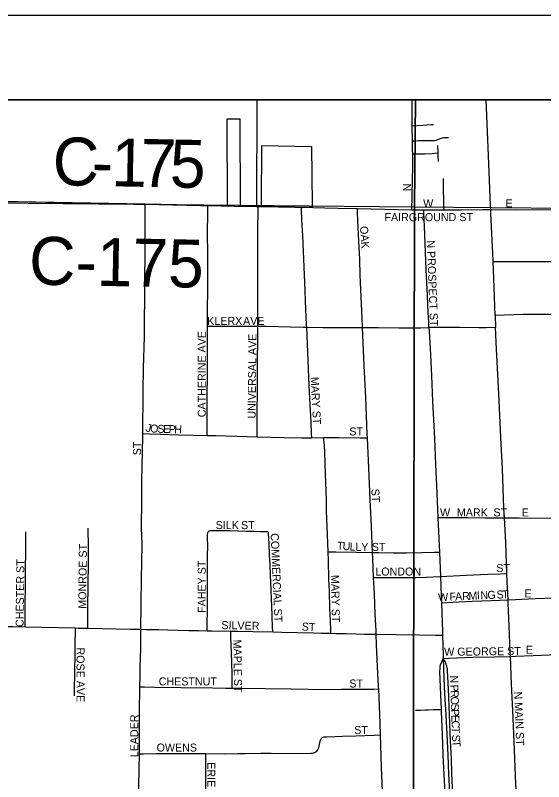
# Model space of a CAD drawing. Extents: x -9.1 to 34, y -3.1 to 22.
# Drawn here: x 4.755 to 5.381, y 20.093 to 21 of the extents above; entities that cross this region are included whole.
import ezdxf

# ---------------------------------------------------------------- set-up
doc = ezdxf.new("R2010")
doc.units = 0
for name, color, linetype in [('GM_X_City_Street', 7, 'Continuous'), ('GM_X_City_Street_Text', 7, 'Continuous'), ('GM_X_Corporation', 7, 'Continuous'), ('GM_X_County_Road', 7, 'Continuous'), ('GM_X_County_Road_Text', 7, 'Continuous'), ('GM_X_Section', 7, 'Continuous'), ('GM_X_State_Route', 7, 'Continuous'), ('SH_Data', 7, 'Continuous')]:
    doc.layers.add(name, color=color, linetype=linetype)

msp = doc.modelspace()

# ---------------------------------------------------------------- linework, layer by layer
at = {"layer": 'GM_X_City_Street'}
for points in [[(5.22551, 20.86936), (5.22535, 20.88109), (5.22533, 20.89662), (5.22534, 20.9)], [(5.22551, 20.86936), (5.23142, 20.86962), (5.23781, 20.86991), (5.24737, 20.87077), (5.25057, 20.8708)], [(5.22575, 20.85146), (5.22551, 20.86936)], [(5.22575, 20.85146), (5.22951, 20.85164), (5.23291, 20.8518), (5.23571, 20.85175), (5.23851, 20.8517), (5.24949, 20.85167), (5.25058, 20.85175), (5.25164, 20.85183), (5.25358, 20.85214), (5.2567, 20.85341), (5.25789, 20.85398), (5.25871, 20.85428), (5.26011, 20.85478), (5.26134, 20.85512), (5.26297, 20.85535), (5.26511, 20.85535), (5.26818, 20.85544)], [(5.22597, 20.836), (5.22589, 20.8408), (5.22575, 20.85146)], [(5.25607, 20.83729), (5.25577, 20.84606)], [(5.22506, 20.76989), (5.22511, 20.77377), (5.22522, 20.78184), (5.22578, 20.80969), (5.22595, 20.81592), (5.22591, 20.82836), (5.226, 20.83454), (5.22597, 20.836)], [(5.22597, 20.836), (5.23091, 20.83597), (5.23989, 20.83592), (5.2489, 20.83659), (5.2519, 20.83688), (5.25607, 20.83729)], [(5.2564, 20.827), (5.25622, 20.83362), (5.25607, 20.83729)], [(5.26304, 20.76986), (5.26293, 20.77345), (5.26274, 20.78039), (5.26259, 20.79335), (5.26251, 20.79976), (5.26243, 20.80683)], [(4.90602, 20.50486), (4.90656, 20.55459), (4.90695, 20.58236), (4.908, 20.61929), (4.90852, 20.68454), (4.90904, 20.72028), (4.90903, 20.75136), (4.90903, 20.77183), (4.90903, 20.77635)], [(4.98285, 20.63214), (4.9829, 20.64625), (4.98294, 20.6548), (4.98304, 20.6718), (4.9831, 20.68226), (4.98314, 20.69724), (4.98311, 20.71109), (4.98308, 20.72191), (4.98296, 20.73741), (4.98312, 20.7703), (4.98315, 20.77476)], [(5.04074, 20.77381), (5.04276, 20.77379)], [(5.04233, 20.63207), (5.04236, 20.63902), (5.04241, 20.65127), (5.0423, 20.66875), (5.0424, 20.68633), (5.0425, 20.70587), (5.0424, 20.72736), (5.04232, 20.74518), (5.0427, 20.76977), (5.04276, 20.77379)], [(5.04276, 20.77379), (5.04737, 20.77376)], [(5.10035, 20.63083), (5.10019, 20.63356), (5.09898, 20.6616), (5.09849, 20.67421), (5.09775, 20.69302), (5.09561, 20.73888), (5.09478, 20.75802), (5.09431, 20.76973), (5.09418, 20.77276)], [(5.10749, 20.77249), (5.12198, 20.77205), (5.1375, 20.77165), (5.15928, 20.77135), (5.16054, 20.77132)], [(5.16651, 20.63046), (5.16602, 20.64144), (5.16372, 20.69253), (5.16312, 20.71101), (5.16228, 20.73259), (5.16105, 20.75722), (5.16071, 20.76651), (5.16054, 20.77132)], [(5.16054, 20.77132), (5.20904, 20.77002), (5.22506, 20.76989)], [(5.22506, 20.76989), (5.23391, 20.76983), (5.23907, 20.76983)], [(5.23907, 20.76983), (5.26304, 20.76986)], [(5.24521, 20.6304), (5.24489, 20.63631), (5.24452, 20.64318), (5.24427, 20.64765), (5.24338, 20.66855), (5.24208, 20.69885), (5.2398, 20.75025), (5.2392, 20.76633), (5.23907, 20.76983)], [(5.26304, 20.76986), (5.28369, 20.76989), (5.30917, 20.77016), (5.31853, 20.77025)], [(5.31853, 20.77025), (5.34775, 20.76989), (5.39737, 20.77016), (5.39918, 20.77018)], [(5.32126, 20.70844), (5.33072, 20.70845), (5.38395, 20.70852), (5.40252, 20.7086)], [(4.98227, 20.50274), (4.98229, 20.50622), (4.98237, 20.5204), (4.98247, 20.53842), (4.98257, 20.55462), (4.98265, 20.56937), (4.98273, 20.58299), (4.98276, 20.60111), (4.9828, 20.61788), (4.98285, 20.63214)], [(4.98285, 20.63214), (4.98731, 20.63214), (5.03057, 20.63214), (5.04233, 20.63207)], [(5.04163, 20.50121), (5.04165, 20.50628), (5.04174, 20.52277), (5.0418, 20.53321), (5.04191, 20.55247), (5.0422, 20.58025), (5.04225, 20.59267), (5.04235, 20.61418), (5.04231, 20.6265), (5.04233, 20.63207)], [(5.04233, 20.63207), (5.05221, 20.63201), (5.08118, 20.63122), (5.09638, 20.63091), (5.10035, 20.63083)], [(5.10035, 20.63083), (5.11935, 20.63067), (5.13499, 20.63063), (5.16651, 20.63046)], [(5.10626, 20.50006), (5.10607, 20.50474), (5.10553, 20.51841), (5.10423, 20.54636), (5.10341, 20.56189), (5.10035, 20.63083)], [(5.16651, 20.63046), (5.16942, 20.63042), (5.18501, 20.63032), (5.2096, 20.63016), (5.22553, 20.63005), (5.23574, 20.62999), (5.24521, 20.6304)], [(5.17236, 20.50007), (5.17216, 20.50434), (5.17031, 20.54762), (5.16859, 20.5851), (5.16732, 20.61254), (5.16651, 20.63046)], [(5.33461, 20.40522), (5.33402, 20.41672), (5.33223, 20.46309), (5.33045, 20.50019), (5.32841, 20.54399), (5.32678, 20.57476), (5.32519, 20.60477), (5.32412, 20.63035)], [(4.90482, 20.3986), (4.90487, 20.42089), (4.90509, 20.44886), (4.90601, 20.50162), (4.90602, 20.50486)], [(4.90602, 20.50486), (4.91394, 20.50459), (4.92718, 20.50415), (4.94897, 20.50348), (4.98227, 20.50274)], [(4.98227, 20.50274), (4.99258, 20.50251), (5.02994, 20.50155), (5.04163, 20.50121)], [(5.04163, 20.50121), (5.0735, 20.50029), (5.09416, 20.49994), (5.10626, 20.50006)], [(5.12035, 20.5002), (5.12166, 20.50021), (5.13872, 20.50041), (5.16361, 20.50008), (5.16671, 20.50008), (5.17236, 20.50007)], [(5.10626, 20.50006), (5.12035, 20.5002)], [(5.12569, 20.36507), (5.12464, 20.39495), (5.12422, 20.4042), (5.12401, 20.41352), (5.12369, 20.42598), (5.1228, 20.45721), (5.12191, 20.48225), (5.12132, 20.49103), (5.12035, 20.5002)], [(5.17838, 20.36421), (5.17706, 20.39489), (5.17553, 20.42699), (5.17402, 20.46409), (5.17236, 20.50007)], [(5.25584, 20.40548), (5.26048, 20.40548), (5.27289, 20.40548), (5.29121, 20.40549), (5.31138, 20.40534), (5.32267, 20.40538), (5.33461, 20.40522)], [(5.33461, 20.40522), (5.3385, 20.40522), (5.35252, 20.40522), (5.36568, 20.405), (5.38586, 20.40508), (5.40301, 20.40493), (5.41499, 20.40452)], [(5.3376, 20.33914), (5.3361, 20.37607), (5.33461, 20.40522)], [(4.84109, 20.27454), (4.84113, 20.27918), (4.8412, 20.28724), (4.84117, 20.29662), (4.8412, 20.30563), (4.84125, 20.31792), (4.84137, 20.33086), (4.84173, 20.34585), (4.8417, 20.35834), (4.84168, 20.37051), (4.84151, 20.39304)], [(4.90387, 20.27331), (4.90408, 20.30295), (4.90454, 20.33315), (4.90483, 20.35268), (4.90529, 20.37429), (4.90481, 20.39292), (4.90482, 20.3986)], [(4.76668, 20.27618), (4.76666, 20.28193), (4.76661, 20.30035), (4.76716, 20.32787), (4.76729, 20.34914), (4.76739, 20.36129), (4.76747, 20.38575), (4.76747, 20.38879)], [(4.98252, 20.27154), (4.98262, 20.28002), (4.98283, 20.2955), (4.98286, 20.31084), (4.9828, 20.3475), (4.98298, 20.35979), (4.98302, 20.37209), (4.98296, 20.38135), (4.98298, 20.38571), (4.983, 20.38643), (4.98308, 20.38713), (4.98324, 20.38765), (4.98344, 20.38813), (4.98392, 20.38898)], [(4.98392, 20.38898), (4.98432, 20.38937), (4.98487, 20.38975), (4.98538, 20.38998), (4.98598, 20.39011), (4.98665, 20.39018), (4.9876, 20.39016), (4.99273, 20.39015), (5.00022, 20.39009), (5.00958, 20.39002), (5.02861, 20.38953), (5.03808, 20.38932), (5.04545, 20.38916), (5.05039, 20.38912), (5.0523, 20.38908), (5.05341, 20.38893), (5.05416, 20.38869), (5.05465, 20.38824)], [(5.06009, 20.27013), (5.05991, 20.27612), (5.05916, 20.3011), (5.05883, 20.30797), (5.05829, 20.31998), (5.05754, 20.33703), (5.057, 20.34969), (5.05642, 20.36118), (5.05582, 20.37485), (5.05517, 20.38684), (5.05497, 20.38767), (5.05465, 20.38824)], [(5.12908, 20.26857), (5.12894, 20.2719), (5.12845, 20.28383), (5.12787, 20.29803), (5.12721, 20.31834), (5.12674, 20.33277), (5.12606, 20.35459), (5.12569, 20.36507)], [(5.12569, 20.36507), (5.12886, 20.36498), (5.13485, 20.36481), (5.15919, 20.36454), (5.17838, 20.36421)], [(5.17838, 20.36421), (5.18529, 20.36406), (5.20274, 20.3638), (5.21856, 20.36374), (5.23659, 20.36404), (5.25181, 20.3645), (5.25758, 20.3647)], [(5.17966, 20.33462), (5.17869, 20.35713), (5.17838, 20.36421)], [(5.25873, 20.33586), (5.28917, 20.33716), (5.31505, 20.33834), (5.32975, 20.33886), (5.3376, 20.33914)], [(5.33887, 20.30775), (5.33798, 20.3295), (5.3376, 20.33914)], [(5.17966, 20.33462), (5.18612, 20.33455), (5.19236, 20.33448), (5.20801, 20.33444), (5.22987, 20.3346), (5.24199, 20.33513), (5.25793, 20.33581), (5.25873, 20.33586)], [(5.18264, 20.26743), (5.18249, 20.27137), (5.18157, 20.2915), (5.1805, 20.31518), (5.17966, 20.33462)], [(5.41873, 20.31105), (5.4052, 20.3105), (5.37122, 20.30913), (5.35541, 20.30845), (5.3479, 20.30813), (5.33887, 20.30775)], [(5.33887, 20.30775), (5.31948, 20.30714), (5.29644, 20.30607), (5.27297, 20.30515), (5.2667, 20.30477), (5.25991, 20.30437)], [(5.34109, 20.25534), (5.34047, 20.26804), (5.339, 20.30435), (5.33887, 20.30775)], [(4.69403, 20.27766), (4.70576, 20.2774), (4.73368, 20.27677), (4.75233, 20.27643), (4.76668, 20.27618)], [(4.76668, 20.27618), (4.78652, 20.27584), (4.82656, 20.27484)], [(4.82515, 20.19451), (4.82535, 20.20704), (4.82552, 20.216), (4.82577, 20.22877), (4.82588, 20.23811), (4.82591, 20.24146), (4.82604, 20.25655), (4.82646, 20.27194), (4.82656, 20.27484)], [(4.82656, 20.27484), (4.82999, 20.27476), (4.84109, 20.27454)], [(4.84109, 20.27454), (4.89178, 20.27354), (4.90387, 20.27331)], [(4.90254, 20.2051), (4.90286, 20.21753), (4.90315, 20.22872), (4.9037, 20.25021), (4.90387, 20.27331)], [(4.90387, 20.27331), (4.91056, 20.27318), (4.92523, 20.27285), (4.93586, 20.27264), (4.94805, 20.27233), (4.96059, 20.272), (4.97203, 20.27171), (4.98252, 20.27154)], [(4.98252, 20.27154), (4.98777, 20.27146), (5.0104, 20.27109)], [(5.01191, 20.2036), (5.01198, 20.20865), (5.0121, 20.21794), (5.01195, 20.22104), (5.01118, 20.24583), (5.0106, 20.26442), (5.0104, 20.27109)], [(5.0104, 20.27109), (5.01884, 20.27095), (5.03697, 20.27065), (5.06009, 20.27013)], [(5.06009, 20.27013), (5.07108, 20.26988), (5.10826, 20.26905), (5.11796, 20.26882), (5.12908, 20.26857)], [(5.12908, 20.26857), (5.13469, 20.26844), (5.1473, 20.26815), (5.15867, 20.26789), (5.16903, 20.26765), (5.17515, 20.26759), (5.18131, 20.26748), (5.18264, 20.26743)], [(5.18563, 20.20265), (5.18552, 20.20534), (5.18438, 20.22913), (5.18314, 20.25493), (5.18264, 20.26743)], [(5.18264, 20.26743), (5.20617, 20.26702), (5.23416, 20.26662), (5.25287, 20.2665), (5.26126, 20.26645)], [(5.34174, 20.24123), (5.34156, 20.24594), (5.34109, 20.25534)], [(5.26001, 20.17842), (5.25809, 20.22273), (5.25831, 20.22729), (5.25863, 20.22913), (5.25898, 20.23106), (5.25988, 20.23403), (5.26212, 20.23884)], [(5.26212, 20.23884), (5.26843, 20.2391), (5.2777, 20.23947), (5.2972, 20.2402), (5.32301, 20.24079), (5.34174, 20.24123)], [(5.27419, 20.0589), (5.27394, 20.0664), (5.27371, 20.07288), (5.27312, 20.08605), (5.27234, 20.10294), (5.27174, 20.11983), (5.27056, 20.14143), (5.26956, 20.17169), (5.26858, 20.19388), (5.26759, 20.21784), (5.26737, 20.22316), (5.26707, 20.22611), (5.26633, 20.22978), (5.26516, 20.23286), (5.26428, 20.23506), (5.26212, 20.23884)], [(5.34174, 20.24123), (5.34778, 20.24148), (5.36868, 20.24234), (5.38812, 20.24302), (5.4224, 20.24474)], [(5.3497, 20.06251), (5.34929, 20.06954), (5.34833, 20.0902), (5.34612, 20.13998), (5.34453, 20.17728), (5.34305, 20.20825), (5.34174, 20.24123)], [(4.90227, 20.12594), (4.90222, 20.14078), (4.9023, 20.15741), (4.90238, 20.17379), (4.90244, 20.18458), (4.90249, 20.19479), (4.90254, 20.2051)], [(4.90254, 20.2051), (4.9081, 20.20503), (4.92031, 20.20486), (4.95146, 20.20451), (4.9888, 20.20387), (5.00423, 20.20369), (5.01191, 20.2036)], [(5.01191, 20.2036), (5.02275, 20.2035), (5.05166, 20.20304), (5.0818, 20.20298), (5.10206, 20.20259), (5.12459, 20.20215), (5.14139, 20.2023), (5.15592, 20.20242), (5.16757, 20.20252), (5.17997, 20.2026), (5.18563, 20.20265)], [(5.18772, 20.14817), (5.18724, 20.16206), (5.18563, 20.20265)], [(5.22912, 20.17752), (5.23523, 20.17755), (5.24125, 20.17775), (5.24418, 20.17793), (5.25031, 20.17816), (5.25798, 20.17836), (5.26001, 20.17842)], [(5.26556, 20.05857), (5.26488, 20.07308), (5.2633, 20.10097), (5.26211, 20.12494), (5.26113, 20.1487), (5.26014, 20.17542), (5.26001, 20.17842)], [(4.98088, 20.12615), (5.00293, 20.12603), (5.01826, 20.12612), (5.02131, 20.12625), (5.02738, 20.12621), (5.04594, 20.12657), (5.0584, 20.12659), (5.09579, 20.12624), (5.10514, 20.12646), (5.10677, 20.12658), (5.10822, 20.12691), (5.10975, 20.1274), (5.11107, 20.1281), (5.11237, 20.12911), (5.11332, 20.13019), (5.1141, 20.1315), (5.11468, 20.13297), (5.11581, 20.13909), (5.11655, 20.14214), (5.11695, 20.1429), (5.1173, 20.14345), (5.11779, 20.14404), (5.11832, 20.14463), (5.11896, 20.1451), (5.11971, 20.14554), (5.12109, 20.14593), (5.1242, 20.14614), (5.1337, 20.14632), (5.14288, 20.14661), (5.15845, 20.1471), (5.18025, 20.1479), (5.18772, 20.14817)], [(5.19111, 20.05537), (5.18999, 20.08168), (5.18905, 20.10951), (5.18815, 20.13574), (5.18772, 20.14817)], [(4.90088, 20.06455), (4.90141, 20.08805), (4.90184, 20.10654), (4.90227, 20.12594)], [(4.90227, 20.12594), (4.90681, 20.12598), (4.92237, 20.12612), (4.94726, 20.12634), (4.96863, 20.12622), (4.98088, 20.12615)], [(4.97985, 20.07208), (4.98005, 20.0723), (4.98016, 20.07257), (4.98022, 20.07285), (4.98033, 20.07384), (4.98045, 20.07584), (4.98084, 20.09149), (4.98078, 20.09461), (4.98088, 20.10402), (4.98088, 20.11974), (4.98088, 20.12615)]]:
    msp.add_lwpolyline(points, dxfattribs=at)
at = {"layer": 'GM_X_Corporation'}
msp.add_line((6.49433, 20.9), (5.04128, 20.9), dxfattribs=at)
for points in [[(5.04128, 20.9), (5.04074, 20.77381), (5.02189, 20.77403), (5.02155, 20.87704), (5.00565, 20.87703), (5.00624, 20.77431), (4.98315, 20.77476), (4.90903, 20.77635), (4.73612, 20.77966), (4.73596, 20.9)], [(5.10615, 20.84481), (5.10674, 20.77628), (5.10677, 20.77273), (5.10677, 20.77249), (5.10675, 20.77249), (5.10666, 20.77249), (5.08666, 20.7729), (5.07022, 20.77318), (5.05374, 20.77347), (5.04668, 20.77359), (5.0467, 20.77738), (5.04719, 20.84593), (5.10615, 20.84481)]]:
    msp.add_lwpolyline(points, dxfattribs=at)
at = {"layer": 'GM_X_County_Road'}
for points in [[(4.73612, 20.77966), (4.74046, 20.77951), (4.77164, 20.77913), (4.83091, 20.77801), (4.90578, 20.77642), (4.90903, 20.77635)], [(4.90903, 20.77635), (4.97441, 20.77489), (4.98315, 20.77476)], [(4.98315, 20.77476), (5.01494, 20.77427), (5.04074, 20.77381)], [(5.04737, 20.77376), (5.08638, 20.77292), (5.09418, 20.77276)], [(5.09418, 20.77276), (5.10749, 20.77249)]]:
    msp.add_lwpolyline(points, dxfattribs=at)
at = {"layer": 'GM_X_Section'}
for p, q in [((5.22924, 20.9), (4.23016, 20.9)), ((6.24144, 20.9), (5.22924, 20.9))]:
    msp.add_line(p, q, dxfattribs=at)
for points in [[(4.23016, 20.9), (4.22892, 20.78268), (5.2279, 20.77322), (5.22924, 20.9)], [(5.22924, 20.9), (5.2279, 20.77322), (6.2403, 20.76479), (6.24144, 20.9)]]:
    msp.add_lwpolyline(points, dxfattribs=at)
for points in [[(4.22892, 20.78268), (5.2279, 20.77322), (5.226, 19.77229), (4.2285, 19.77719)], [(5.2279, 20.77322), (6.2403, 20.76479), (6.2379, 19.76083), (5.226, 19.77229)]]:
    msp.add_lwpolyline(points, close=True, dxfattribs=at)
at = {"layer": 'GM_X_State_Route'}
for points in [[(5.31832, 20.77523), (5.31587, 20.83424), (5.31285, 20.9)], [(5.32366, 20.64482), (5.32259, 20.67771), (5.32126, 20.70844), (5.32119, 20.70984), (5.31871, 20.7658), (5.31853, 20.77025), (5.31832, 20.77523)], [(5.40449, 20.64596), (5.39923, 20.64588), (5.38476, 20.64593), (5.35698, 20.64569), (5.32366, 20.64482)], [(5.32366, 20.64482), (5.32412, 20.63035), (5.31313, 20.63027)], [(5.31313, 20.63027), (5.30426, 20.6302), (5.28223, 20.63042), (5.26003, 20.63063), (5.25127, 20.63063), (5.24521, 20.6304), (5.24561, 20.62624), (5.24669, 20.60554)], [(5.24669, 20.60554), (5.24707, 20.59828), (5.24806, 20.57345), (5.24955, 20.54316), (5.25171, 20.49907), (5.253, 20.46819), (5.25459, 20.43426), (5.25584, 20.40548), (5.25727, 20.37259), (5.25758, 20.3647), (5.25873, 20.33586), (5.25915, 20.32543), (5.25966, 20.31126)], [(5.25966, 20.31126), (5.25991, 20.30437), (5.26114, 20.27032), (5.26126, 20.26645), (5.26199, 20.24235), (5.26212, 20.23884)], [(5.26212, 20.23884), (5.26342, 20.20507), (5.26452, 20.18336), (5.26473, 20.17901)], [(5.26473, 20.17901), (5.2662, 20.14933), (5.26739, 20.12446), (5.26848, 20.10275), (5.26919, 20.08765), (5.27009, 20.06595), (5.27033, 20.06057), (5.2704, 20.05875), (5.27106, 20.04227), (5.27222, 20.01011), (5.27296, 19.98939), (5.27365, 19.96559)]]:
    msp.add_lwpolyline(points, dxfattribs=at)
at = {"layer": 'SH_Data'}
for p, q in [((2.5, 21), (9.5, 21)), ((2.6, 20.9), (9.4, 20.9))]:
    msp.add_line(p, q, dxfattribs=at)

# ---------------------------------------------------------------- texts
at = {"layer": 'GM_X_City_Street_Text'}
for s, height, rotation, p in [('N', 0.00947, 90, (5.22407, 20.79175)), ('W', 0.00947, 0.00001, (5.23835, 20.7727)), ('E', 0.00947, 0.00001, (5.33585, 20.7727)), ('FAIRGROUND ST', 0.0094697, 0.00001, (5.19251, 20.75641)), ('OAK', 0.00947, 273.81941, (5.16345, 20.75021)), ('N PROSPECT ST', 0.0094697, 272.24512, (5.24263, 20.73343)), ('KLERX', 0.00947, 0.00001, (4.98251, 20.63353)), ('AVE', 0.00947, 0.00001, (5.02501, 20.63354)), ('CATHERINE AVE', 0.0094697, 90, (4.98073, 20.52425)), ('UNIVERSAL AVE', 0.0094697, 89.48903, (5.03989, 20.52257)), ('MARY ST', 0.00947, 272.81756, (5.10512, 20.57184)), ('J', 0.00947, 347.53282, (4.90898, 20.5076)), ('O', 0.00947, 355.75902, (4.91452, 20.50648)), ('S', 0.00947, 358.77635, (4.92337, 20.50584)), ('E', 0.00947, 358.77067, (4.93004, 20.5057)), ('P', 0.00947, 358.80125, (4.93671, 20.50555)), ('H', 0.00947, 358.77601, (4.94337, 20.50541)), ('ST', 0.00947, 0.00001, (5.15085, 20.5027)), ('ST', 0.00947, 90, (4.90406, 20.47925)), ('ST', 0.00947, 273.57465, (5.17679, 20.43936)), ('W', 0.00947, 0.00001, (5.25834, 20.40686)), ('MARK', 0.00947, 0.00001, (5.27835, 20.40687)), ('ST', 0.00947, 0.00001, (5.32168, 20.40687)), ('E', 0.00947, 0.00001, (5.35501, 20.40686)), ('SILK', 0.00947, 0.00001, (4.99251, 20.39187)), ('ST', 0.00947, 0.00001, (5.02251, 20.39187)), ('COMMERCIAL ST', 0.0094697, 272.46729, (5.05763, 20.38681)), ('MONROE ST', 0.00947, 89.28503, (4.83906, 20.29756)), ('T', 0.00947, 355.95331, (5.13597, 20.3677)), ('U', 0.00947, 355.95219, (5.14262, 20.36723)), ('L', 0.00947, 356.33629, (5.151, 20.36664)), ('L', 0.00947, 358.72227, (5.15808, 20.36619)), ('Y', 0.00947, 359.94602, (5.16496, 20.36604)), ('ST', 0.00947, 0.00001, (5.17751, 20.36604)), ('CHESTER ST', 0.00947, 89.3025, (4.7649, 20.27589)), ('FAHEY ST', 0.00947, 90, (4.98073, 20.29259)), ('LONDON', 0.00947, 0.00001, (5.18168, 20.33687)), ('ST', 0.00947, 0.00001, (5.32501, 20.34104)), ('MARY ST', 0.00947, 270.94073, (5.12929, 20.33755)), ('G', 0.00947, 2.60832, (5.31469, 20.30906)), ('S', 0.00947, 2.59636, (5.32551, 20.30955)), ('T', 0.00947, 2.60347, (5.33217, 20.30985)), ('E', 0.00947, 0.00001, (5.35834, 20.31103)), ('W', 0.00947, 4.39226, (5.25651, 20.30603)), ('F', 0.00947, 2.67823, (5.26974, 20.307)), ('A', 0.00947, 2.60157, (5.27639, 20.30731)), ('R', 0.00947, 2.60606, (5.28472, 20.30769)), ('M', 0.00947, 2.60587, (5.29221, 20.30803)), ('I', 0.00947, 2.62202, (5.3022, 20.30849)), ('N', 0.00947, 2.60157, (5.30636, 20.30868)), ('SILVER', 0.00947, 358.82876, (4.99922, 20.27354)), ('ST', 0.00947, 356.42537, (5.09429, 20.27186)), ('MAPLE ST', 0.00947, 270.84084, (5.01346, 20.26097)), ('ROSE AVE', 0.00947, 270, (4.82763, 20.25175)), ('W GEORGE ST', 0.0094697, 0.62193, (5.26331, 20.24187)), ('E', 0.00947, 0.00001, (5.36001, 20.24436)), ('CHESTNUT', 0.00947, 0.00001, (4.92501, 20.20687)), ('ST', 0.00947, 0.00001, (5.15085, 20.20437)), ('N', 0.00947, 271.88003, (5.27012, 20.21848)), ('P', 0.00947, 271.8855, (5.27048, 20.20765)), ('R', 0.00947, 271.87032, (5.2707, 20.20099)), ('O', 0.00947, 271.89696, (5.27094, 20.19348)), ('N MAIN ST', 0.00947, 272.4527, (5.34596, 20.19933)), ('S', 0.00947, 271.90218, (5.27122, 20.18515)), ('P', 0.00947, 271.90218, (5.27144, 20.17849)), ('LEADER', 0.00947, 90, (4.90073, 20.12175)), ('E', 0.00947, 271.8855, (5.27166, 20.17183)), ('C', 0.00947, 271.87032, (5.27188, 20.16517)), ('ST', 0.00947, 0.00001, (5.15668, 20.14937)), ('T', 0.00947, 271.90218, (5.27212, 20.15766)), ('S', 0.00947, 272.67853, (5.27243, 20.14836)), ('OWENS', 0.00947, 0.00001, (4.92251, 20.12854)), ('T', 0.00947, 275.0695, (5.27277, 20.14127)), ('ERIE ST', 0.00947, 270, (4.98263, 20.11592))]:
    msp.add_text(s, height=height, rotation=rotation, dxfattribs=at).set_placement(p)
at = {"layer": 'GM_X_County_Road_Text'}
for s, height, rotation, p in [('C', 0.05682, 358.86447, (4.79896, 20.79907)), ('1', 0.05682, 358.86446, (4.86839, 20.79769)), ('7', 0.05682, 358.86497, (4.90311, 20.797)), ('5', 0.05682, 358.88254, (4.93784, 20.79632)), ('-', 0.05682, 358.86446, (4.84527, 20.79815)), ('C-175', 0.056818, 358.90348, (4.771, 20.6814))]:
    msp.add_text(s, height=height, rotation=rotation, dxfattribs=at).set_placement(p)

doc.saveas('drawing.dxf')
